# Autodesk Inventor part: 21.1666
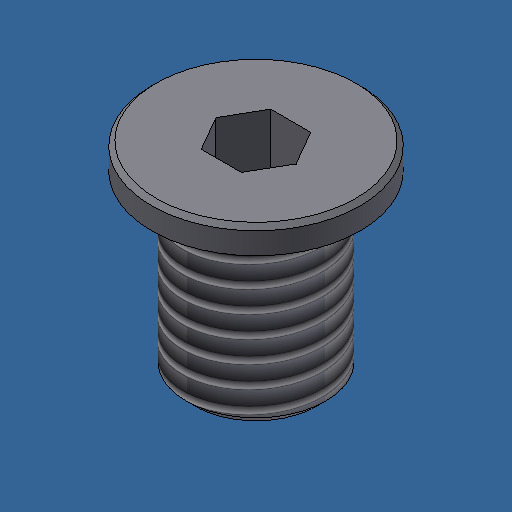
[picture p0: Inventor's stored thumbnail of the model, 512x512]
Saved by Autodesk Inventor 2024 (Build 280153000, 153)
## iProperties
Created: 2009-05
Part Number: 21.1666
Material: Stainless Steel
Document SubType Name: Modeling
Designer: Administrator
Mass: 4.75031 g
Surface Area: 5.96938 cm^2
Volume: 0.58791 cm^3
Density: 8.08 g/cm^3
Description: M8x10 Stainless Extra Low Head
Vendor: S
Appearance: Steel
Author: Administrator
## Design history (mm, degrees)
sketch "Sketch1"
  geometry: C1 r 6 at (0, 0); 1 further point
  constraints: 1 centre point, 1 coincident
  dimensions: "d0" = 12 diameter of C1
extrude "Extrusion1" new body sketch "Sketch1" distance "d1" = 1.5; taper "d2" = 0 deg
sketch "Sketch2"
  geometry: C1 r 6 at (0, 0) reference; C2 r 4 at (0, 0)
  constraints: 1 centre point, 1 coincident
  dimensions: "d3" = 8 diameter of C2
extrude "Extrusion2" join sketch "Sketch2" distance "d4" = 10; taper "d5" = 0 deg
thread "Thread1" dims "d6" = 23, "d7" = 0
sketch "Sketch3"
  geometry: L1 (-1.155, 2)-(1.155, 2); L2 (1.155, 2)-(2.309, 0); L3 (2.309, 0)-(1.155, -2); L4 (1.155, -2)-(-1.155, -2); L5 (-1.155, -2)-(-2.309, 0); L6 (-2.309, 0)-(-1.155, 2); C1 r 6 at (0, 0) reference; 1 further point
  constraints: 12 end point, 3 parallel, 2 equal length, 2 horizontal alignment, 1 horizontal, 1 midpoint, 1 vertical alignment
  dimensions: "d8" = 120 deg angle of L2 L1; "d9" = 120 deg angle of L3 L2; "d10" = 4 distance between parallel lines of L3 L6
extrude "Extrusion3" cut sketch "Sketch3" distance "d11" = 5; taper "d12" = 0 deg
sketch "Sketch4"
  geometry: L1 (0, -5)-(2, -5) reference; L2 (2, -5)-(0, -5); L3 (0, -6.5)-(0.5, -6.5); L4 (0, -5)-(0, -6.5); L5 (0.915, -6.368)-(0.085, -6.632); A1 r 2.131 centre (-0.146, -4.47) between (0.164, -6.578) and (0.819, -6.369); 1 further point
  constraints: 8 end point, 2 midpoint, 1 centre point, 1 collinear, 1 parallel, 1 perpendicular, 1 point on circle, 4 other
  dimensions: "d13" = 1.5 distance of L1.start L3.start; "d14" = 0.5 distance of L3.start L3.end
revolve "Revolution1" sketch "Sketch4" stored, may be unused: angle "d15" = 90 deg
chamfer "Chamfer1" distance "d16" = 0.25; stored, may be unused: second distance "d17" = 2, angle "d18" = 45 deg
chamfer "Chamfer2" distance "d19" = 0.5; stored, may be unused: second distance "d20" = 2, angle "d21" = 45 deg
body "Solid1"
